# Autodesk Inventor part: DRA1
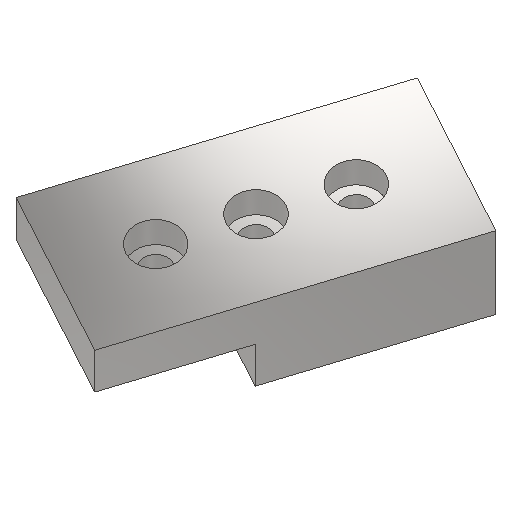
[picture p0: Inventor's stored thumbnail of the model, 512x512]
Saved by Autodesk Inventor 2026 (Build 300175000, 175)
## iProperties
Created: 2004-10
Part Number: DRA1
Document SubType Name: Modeling
Designer: Bo Hansen
Manufacturer: Standard
Standards Organization: Custom
Material: Steel, Mild
Density: 7.85 g/cm^3
Appearance: Semi-Polished
Author: Bo Hansen
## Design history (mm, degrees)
sketch "Sketch1"
  geometry: L1 (0, 30)-(100, 30); L2 (100, 30)-(100, 0); L3 (100, 0)-(40, 0); L4 (40, 0)-(40, 15); L5 (40, 15)-(0, 15); L6 (0, 30)-(0, 15); 1 further point
  constraints: 12 end point, 3 parallel, 2 perpendicular, 1 horizontal, 1 horizontal alignment, 1 vertical alignment
  dimensions: "d0" = 100 distance of L1.start L1.end; "d1" = 60 distance of L2.end L3.end; "d2" = 30 distance of L1.end L2.end; "d3" = 15 distance of L1.start L5.end
extrude "Extrusion1" new body sketch "Sketch1" distance "d4" = 50; taper "d5" = 0 deg
sketch "Sketch2"
  geometry: L1 (0, -50)-(100, -50) reference; L2 (0, 0)-(0, -50) reference; 3 further points
  constraints: 2 horizontal alignment
  dimensions: "d18" = 25 distance from line of point (25, -25) L1; "d19" = 25 distance from line of point (25, -25) L2; "d20" = 25 distance of point (25, -25) point (50, -25); "d21" = 25 distance of point (75, -25) point (50, -25)
hole "Hole2" sketch "Sketch2" diameter "d22" = 9; stored, may be unused: countersink angle "d26" = 82 deg, drill point angle "d28" = 118 deg; dims "d23" = 6, "d24" = 15, "d25" = 9, "d27" = 25
hole "Hole1" diameter "d8" = 13.917; stored, may be unused: countersink angle "d12" = 90 deg, drill point angle "d14" = 120 deg; dims "d6" = 25, "d7" = 25, "d9" = 30, "d10" = 20, "d11" = 8, "d13" = 20
pattern_linear "Rectangular Pattern1" dims "d17" = 25
body "Solid1"
